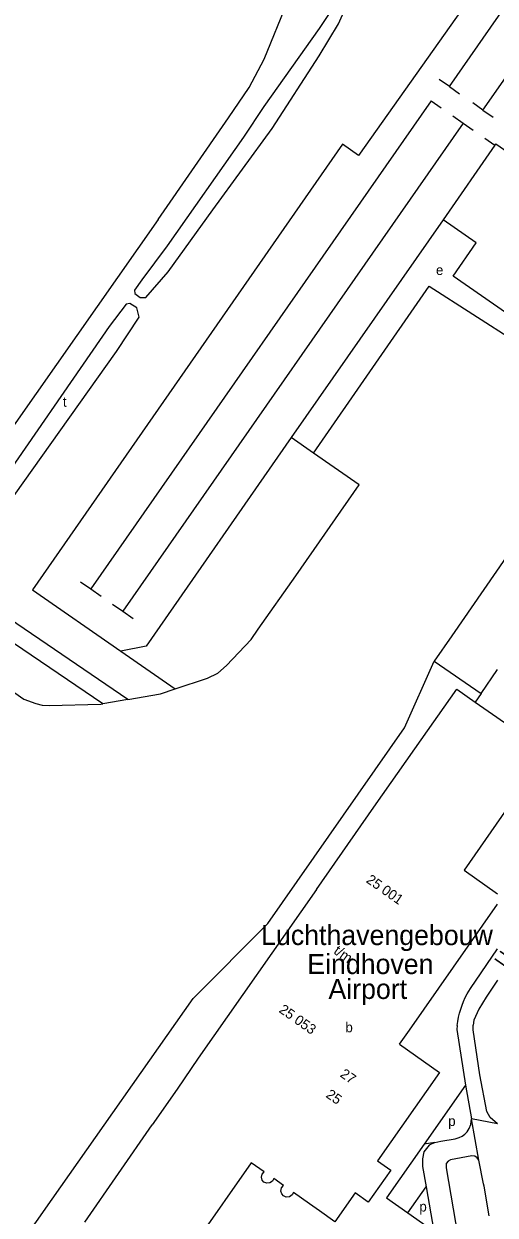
# Model space of a CAD drawing. Extents: x 154765 to 156627, y 383996 to 386132.
# Drawn here: x 155210.2 to 155399, y 385414.8 to 385891.7 of the extents above; entities that cross this region are included whole.
import ezdxf

# ---------------------------------------------------------------- set-up
doc = ezdxf.new("R2010")
doc.units = 0
for name, color, linetype in [('BLT_Basislijn', 7, 'Continuous'), ('BLT_Bebouwing', 7, 'Continuous'), ('BLT_Bebouwing_beschrifting', 7, 'Continuous'), ('BLT_Centroide', 7, 'Continuous'), ('BLT_Huisnummer_reeks', 7, 'Continuous'), ('BLT_Straatnaam', 7, 'Continuous'), ('BLT_Vlakafsluiter', 7, 'Continuous')]:
    doc.layers.add(name, color=color, linetype=linetype)

msp = doc.modelspace()

# ---------------------------------------------------------------- linework, layer by layer
at = {"layer": 'BLT_Basislijn'}
for p, q in [((155380.66, 385866.57), (155434.78, 385944.18)), ((155394.1, 385857.19), (155450.89, 385938.64)), ((155380.66, 385866.57), (155376.56, 385869.43)), ((155380.66, 385866.57), (155384.76, 385863.71)), ((155373.34, 385860.92), (155237.1, 385665.5)), ((155373.34, 385860.92), (155377.44, 385858.06)), ((155394.1, 385857.19), (155390, 385860.05)), ((155382.03, 385854.86), (155386.14, 385852)), ((155394.1, 385857.19), (155398.2, 385854.33)), ((155386.14, 385852), (155249.89, 385656.57)), ((155386.14, 385852), (155390.24, 385849.14)), ((155394.83, 385845.93), (155398.93, 385843.08)), ((155398.93, 385843.08), (155378.18, 385813.31)), ((155378.18, 385813.31), (155317.36, 385726.07)), ((155434.78, 385754.2), (155382.19, 385790.75)), ((155326.29, 385719.84), (155317.36, 385726.07)), ((155304.15, 385649.37), (155319.14, 385670.81)), ((155232.99, 385668.36), (155237.1, 385665.5)), ((155237.1, 385665.5), (155241.2, 385662.64)), ((155245.79, 385659.43), (155249.89, 385656.57)), ((155249.89, 385656.57), (155253.99, 385653.72)), ((155393.38, 385623.63), (155391.01, 385620.24)), ((155383.82, 385490.77), (155383.67, 385489.11)), ((155383.67, 385489.11), (155387.1, 385466.88)), ((155387.1, 385466.88), (155370.54, 385443.23)), ((155387.1, 385466.88), (155389.47, 385453.36)), ((155374.9, 385443.94), (155370.54, 385443.23)), ((155394.4, 385427.34), (155392.42, 385436.89)), ((155364.08, 385415.71), (155371.37, 385426.14)), ((155371.37, 385426.14), (155374.46, 385408.44)), ((155394.55, 385426.48), (155394.4, 385427.34)), ((155396.62, 385414.57), (155394.55, 385426.48)), ((155364.08, 385415.71), (155374.46, 385408.44))]:
    msp.add_line(p, q, dxfattribs=at)
for points in [[(155263.99, 385813.43), (155292.2, 385854.09), (155300.48, 385866.24), (155306.55, 385877.56), (155315.92, 385900.77), (155323.01, 385918.58), (155327.4, 385929.89), (155352.69, 385995.81)], [(155428.86, 385958.6), (155344.28, 385839.05), (155337.84, 385843.61), (155213.78, 385665.15), (155249.03, 385640.64)], [(155333.39, 385897.01), (155328.55, 385889.78), (155306.38, 385858.64), (155298.19, 385846.39), (155267.59, 385802.83), (155257.44, 385789.27), (155254.57, 385785.08), (155254.69, 385783.71), (155256.9, 385782.21), (155259.05, 385782.21), (155268.07, 385792.43), (155285.88, 385817.29), (155309.66, 385849.86), (155328.55, 385878.84), (155336.31, 385891.69), (155339.12, 385897.96)], [(155398.93, 385843.08), (155399.32, 385843.64), (155413.7, 385833.64), (155412.85, 385832.42)], [(155263.99, 385813.43), (155174.31, 385685.7)], [(155382.19, 385790.75), (155391.44, 385804.06), (155378.18, 385813.31)], [(155326.29, 385719.84), (155372.64, 385786.64), (155425.08, 385753.07), (155406.09, 385725.78)], [(155317.36, 385726.07), (155259.19, 385642.63), (155249.03, 385640.64)], [(155319.14, 385670.81), (155344.55, 385707.14), (155326.29, 385719.84)], [(155251.92, 385621.3), (155177.96, 385671.49), (155175.35, 385674.07), (155174.17, 385676.1), (155173.46, 385678.13), (155173.17, 385680.09), (155173.16, 385682.3), (155173.51, 385683.65), (155174.31, 385685.7)], [(155241.85, 385619.55), (155173.97, 385665.6), (155171.25, 385667.04), (155169.08, 385667.7), (155167.41, 385667.89), (155165.87, 385667.85), (155164.26, 385667.57), (155162.8, 385667.03), (155161.24, 385666.07), (155160.08, 385665.07), (155158.61, 385663.34)], [(155270.81, 385625.5), (155283.77, 385629.76), (155287.91, 385631.83), (155291.43, 385634.86), (155301.29, 385645.27), (155304.15, 385649.37)], [(155249.03, 385640.64), (155270.81, 385625.5)], [(155001.53, 385107.93), (155095.72, 385242.01), (155221.63, 385421.26), (155278.06, 385501.59), (155307.92, 385531.59), (155362.73, 385609.97), (155374.64, 385636.58)], [(155206.7, 385623.89), (155210.27, 385621.44), (155215.01, 385619.67), (155217.62, 385619.04), (155220.38, 385618.79), (155241.06, 385619.41), (155241.85, 385619.55)], [(155251.92, 385621.3), (155264.96, 385623.58), (155270.81, 385625.5)], [(155383.82, 385490.77), (155384.04, 385492.42), (155384.35, 385494.06), (155384.74, 385495.68), (155385.2, 385497.29), (155385.74, 385498.86), (155386.35, 385500.42), (155387.04, 385501.93), (155387.8, 385503.42), (155389.15, 385505.62), (155400, 385521.46)], [(155400, 385508.92), (155395.45, 385502.1), (155392.4, 385497.33), (155390.49, 385492.93), (155390.21, 385490.83)], [(155400, 385451.33), (155397.05, 385453.93), (155395.65, 385456.27), (155392.92, 385471.02), (155390.15, 385489.01), (155390.21, 385490.83)], [(155374.9, 385443.94), (155377.28, 385444.4), (155382.98, 385445.33), (155384.61, 385445.86), (155385.83, 385446.47), (155386.85, 385447.2), (155387.75, 385448.19), (155388.63, 385449.52), (155389.26, 385451.12), (155389.47, 385453.36)], [(155370.54, 385443.23), (155355.48, 385421.73), (155364.08, 385415.71)], [(155374.9, 385443.94), (155372.51, 385442.79), (155370.5, 385440.22), (155369.86, 385437.45), (155369.95, 385434.28), (155371.37, 385426.14)], [(155392.42, 385436.89), (155391.77, 385437.82), (155390.87, 385438.4), (155389.63, 385438.52), (155381.11, 385437.02), (155380.12, 385436.47), (155379.44, 385435.48), (155379.34, 385433.81), (155386.86, 385389.98)]]:
    msp.add_lwpolyline(points, dxfattribs=at)
msp.add_lwpolyline([(155251.17, 385779.48), (155244.4, 385770.54), (155196.32, 385701.19), (155181.42, 385679.93), (155179.25, 385676), (155180.61, 385673.29), (155183.59, 385672.89), (155187.52, 385676.68), (155247.38, 385760.52), (155256.46, 385774.33), (155255.51, 385777.99), (155252.66, 385779.75)], close=True, dxfattribs=at)
at = {"layer": 'BLT_Bebouwing'}
for p, q in [((155383.59, 385625.43), (155391.01, 385620.24)), ((155391.01, 385620.24), (155419.58, 385600.25)), ((155327.41, 385545.17), (155280.12, 385477.65)), ((155360.68, 385483.22), (155364.66, 385488.9)), ((155234.74, 385412.07), (155261.63, 385451)), ((155301.33, 385435.8), (155279.2, 385404.25)), ((155328.66, 385416.58), (155324.66, 385419.4))]:
    msp.add_line(p, q, dxfattribs=at)
for points in [[(155426.25, 385670.81), (155426.2, 385670.85), (155407.34, 385683.88), (155381.71, 385646.8)], [(155381.71, 385646.8), (155374.64, 385636.58)], [(155374.64, 385636.58), (155393.38, 385623.63)], [(155393.38, 385623.63), (155400, 385633.24)], [(155366.85, 385601.5), (155383.59, 385625.43)], [(155327.41, 385545.17), (155350.47, 385578.09), (155366.85, 385601.5)], [(155419.58, 385600.25), (155386.53, 385553), (155400, 385543.41)], [(155364.66, 385488.9), (155400, 385539.35)], [(155360.68, 385483.22), (155376.75, 385471.96), (155351.89, 385436.53)], [(155280.12, 385477.65), (155271.69, 385465.3), (155261.63, 385451)], [(155324.66, 385419.4), (155318.22, 385423.94), (155317.65, 385422.91), (155316.63, 385422.21), (155315.37, 385422.09), (155314.29, 385422.53), (155313.57, 385423.31), (155313.21, 385424.5), (155313.47, 385425.74), (155314.3, 385426.7), (155310.36, 385429.47), (155309.8, 385428.44), (155308.77, 385427.75), (155307.61, 385427.61), (155306.41, 385428.09), (155305.71, 385428.87), (155305.38, 385430.1), (155305.65, 385431.28), (155306.46, 385432.2), (155301.33, 385435.8)], [(155351.89, 385436.53), (155357.19, 385432.81), (155348.18, 385419.98)], [(155348.18, 385419.98), (155342.9, 385423.71), (155334.85, 385412.23), (155328.66, 385416.58)]]:
    msp.add_lwpolyline(points, dxfattribs=at)
at = {"layer": 'BLT_Vlakafsluiter'}
for p, q in [((155251.92, 385621.3), (155241.85, 385619.55)), ((155400, 385451.33), (155389.47, 385453.36)), ((155392.42, 385436.89), (155389.47, 385453.36))]:
    msp.add_line(p, q, dxfattribs=at)

# ---------------------------------------------------------------- texts
at = {"layer": 'BLT_Bebouwing_beschrifting'}
for s, p in [('Luchthavengebouw', (155305.28, 385522.97)), ('Eindhoven', (155323.75, 385511.37)), ('Airport', (155332.23, 385501.39))]:
    msp.add_text(s, height=8, rotation=359.9654, dxfattribs=at).set_placement(p)
at = {"layer": 'BLT_Centroide'}
for s, p in [('e', (155375.3, 385791.17)), ('t', (155225.9, 385738.43)), ('b', (155339.02, 385488.04)), ('p', (155380.19, 385450.52)), ('p', (155368.65, 385416.3))]:
    msp.add_text(s, height=4, dxfattribs=at).set_placement(p)
at = {"layer": 'BLT_Huisnummer_reeks'}
for s, rotation, p in [('25 001', 325.0689, (155347.02, 385548.28)), ('t/m', 325.0689, (155334, 385519.84)), ('25 053', 325.0689, (155312.1, 385496.31)), ('27', 324.9894, (155336.59, 385470.52)), ('25', 324.9894, (155330.9, 385462.3))]:
    msp.add_text(s, height=4, rotation=rotation, dxfattribs=at).set_placement(p)
at = {"layer": 'BLT_Straatnaam'}
msp.add_text('LUCHTHAVENWEG', height=5, rotation=55.0452, dxfattribs=at).set_placement((155402.42, 385513.91))

doc.saveas('drawing.dxf')
